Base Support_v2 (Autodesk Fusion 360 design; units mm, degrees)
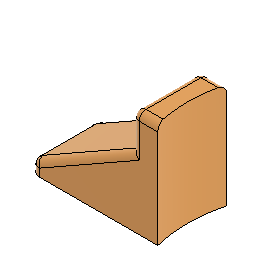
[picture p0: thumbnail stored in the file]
sketch "Sketch1" plane through (0, 0, 0) normal (0, 0, 1) x axis (1, 0, 0)
  line L1 (-5, -10) -> (5, -10)
  line L2 (-5, 10) -> (-5, -10)
  line L3 (5, 10) -> (-5, 10)
  line L4 (5, -10) -> (5, 10)
  line L5 (-5, 10) -> (5, -10)
  line L6 (5, 10) -> (-5, -10)
  point P6 (0, 0)
  point P1 (0, 0)
  point P4 (-5, 10)
  point P5 (5, 10)
  point P3 (-5, -10)
  horizontal L1
  perpendicular L1 L2
  parallel L1 L3
  parallel L2 L4
  coincident L5 P6
  coincident L6 P6
  coincident P1 P6
  dimension "d1" distance P4 P5 = 10
  dimension "d2" distance P3 P4 = 20
extrude "Extrude1" new body sketch "Sketch1" profile of L1 L2 L3 L4 along normal blind 30.7
sketch "Sketch2" plane through (-5, 0, 0) normal (-1, 0, 0) x axis (0, -1, 0)
  line L1 (10, 0) -> (-10, 0)
  line L2 (10, 30.7) -> (10, 0)
  line L3 (-10, 30.7) -> (10, 30.7)
  line L4 (-10, 0) -> (-10, 30.7)
  line L5 (10, 20) -> (-10, 20)
  point P6 (-10, 20)
  point P7 (10, 20)
  coincident L4 P6
  coincident L2 P7
  perpendicular L2 L5
  dimension "d5" distance L1 L5 = 20
extrude "Extrude2" add sketch "Sketch2" profile of L1 L2 L4 L5 along normal blind 30
sketch "Sketch3" plane through (0, -10, 0) normal (0, -1, 0) x axis (1, 0, 0)
  line L1 (5, 0) -> (-35, 0)
  line L2 (5, 30.7) -> (5, 0)
  line L3 (-5, 30.7) -> (5, 30.7)
  line L4 (-5, 20) -> (-5, 30.7)
  line L5 (-35, 20) -> (-5, 20)
  line L6 (-35, 0) -> (-35, 20)
  line L7 (-35, 2.9542) -> (-5, 20)
  point P6 (-5, 20)
  point P8 (-5, 20)
  point P9 (-35, 2.9542)
  coincident P6 P8
  coincident L6 P9
extrude "Extrude3" cut sketch "Sketch3" profile of L5 L6 against normal blind 20
sketch "Sketch4" plane through (0, 0, 30.7) normal (0, 0, 1) x axis (-1, 0, 0)
  line L1 (5, -10) -> (-5, -10)
  line L2 (5, 10) -> (5, -10)
  line L3 (-5, 10) -> (5, 10)
  line L4 (-5, -10) -> (-5, 10)
  circle C1 centre (-41.18, 0) radius 40
  dimension "d10" diameter C1 = 80
extrude "Extrude4" cut sketch "Sketch4" profile of L1 L3 L4 C1 against normal blind 40
fillet "Fillet1" radius 2
fillet "Fillet2" radius 2
fillet "Fillet3" radius 3
fillet "Fillet4" radius 2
